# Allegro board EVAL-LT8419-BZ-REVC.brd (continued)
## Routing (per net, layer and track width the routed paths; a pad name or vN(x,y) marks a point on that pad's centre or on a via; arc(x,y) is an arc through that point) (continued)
SAC2: length 72
  TOP w0.203: C742.1 115,46.44 115.55,45.89 U7.22 ; R459.1 115.56,49.88
  L7_SIG w0.508: v1(58.05,61.13) 58.05,59.24 59.46,57.82 88.6,57.82 98.4,48.02 111.85,48.02 112.22,48.39 v3(115,48.39)
  BOTTOM w0.508: v1(58.05,61.13) 56.17,63.01 R717.2
SAC3: length 35.6
  TOP w0.203: C776.1 113.81,46.44 115.05,45.2 U7.23
  L7_SIG w0.508: v1(87.39,64.28) 87.42,64.31 88.35,64.31 88.79,63.88 88.79,60.83 92.12,57.5 107.21,57.5 111.43,53.28 v3(111.43,51.58)
SAC4: length 56.4
  TOP w0.203: v3(115.4,28.99) 115.36,29.03 C826.1 115.05,29.95 U7.58
  L6_SIG w0.508: v1(121.05,63.62) 121.08,63.65 121.9,63.65 123.27,62.28 123.27,48.09 118.03,42.85 118.03,37.65 117.22,36.83 111.25,36.83 109.58,35.17 109.58,33.31 108.71,32.44 108.71,30.07 109.79,28.99 v3(115.4,28.99)
  BOTTOM w0.203: v1(121.05,63.62) 120.78,63.9 R807.2
SAC5: length 62.7
  TOP w0.203: U7.59 115.55,31.42 116.55,30.42 v3(116.55,29.65)
  L7_SIG w0.508: v3(116.55,29.65) 118.23,29.65 120.86,32.27 128.45,32.27 140.54,44.36 145.18,44.36 146.27,45.44 146.27,52.12 155.05,60.9 v1(155.05,63.61)
  BOTTOM w0.203: R819.2 v1(155.05,63.61)
SAC6: length 91.7
  TOP w0.203: v3(124.19,29.07) 124.2,29.08 C896.1 124.2,29.67 121.28,32.59 U7.64
  L7_SIG w0.508: v1(185.56,63.09) 184.83,62.36 180.08,62.36 173.17,55.44 173.17,42.88 165.07,34.78 135.45,34.78 129.74,29.07 v3(124.19,29.07)
  BOTTOM w0.203: R830.2 v1(185.56,63.09)
SCL: length 149.3
  TOP w0.203: v3(107.5,38.1) 107.62,38.23 107.62,38.33 107.88,38.59 U7.40
  L6_SIG w0.203: v1(5.56,14.28) 5.56,17.01 3.95,18.61 3.95,44.21 E29.1
  L7_SIG w0.203: v1(5.56,14.28) 6.35,13.49 9.12,13.49 11.23,15.6 19.44,15.6 20.82,16.99 30.17,16.99 36.76,23.59 65.74,23.59 76.26,34.11 102.62,34.11 105.95,37.44 107.07,37.44 107.5,37.87 v3(107.5,38.1)
  BOTTOM w0.203: R415.2 v1(5.56,14.28)
SDA: length 158.2
  TOP w0.203: U7.39 107.72,39.09 107.39,38.76 107.39,38.66 107.04,38.3 107.04,38.15 v3(106.99,38.1)
  L6_SIG w0.203: v1(8.7,14.28) 8.14,14.84 6.9,14.84 6.57,14.51 6.57,14.5 5.79,13.72 5.33,13.72 5,14.05 5,16.99 3.55,18.44 3.55,51.42 E32.1
  L7_SIG w0.203: v1(8.7,14.28) 10.51,16.09 19.28,16.09 20.67,17.48 29,17.48 35.61,24.1 65.67,24.1 76.09,34.52 102.39,34.52 105.73,37.85 106.74,37.85 v3(106.99,38.1)
  BOTTOM w0.203: R12.2 v1(8.7,14.28)
SDC1: length 11
  TOP w0.203: R458.2 120.83,51.08 120.5,50.76 119.95,50.76 119.57,50.38 R708.2 119.23,49.88 119.03,49.68 119.03,47.79 119.8,47.01 C14.1 119.83,46.35 119,45.52 117.7,45.52 117.05,44.87 U7.19
SDC2: length 9.6
  TOP w0.203: R459.2 116.83,51.08 117.21,50.7 117.75,50.7 118.07,50.38 R719.2 118.42,49.88 118.62,49.68 118.62,47.79 117.84,47.01 C743.1 117.82,46.44 117.21,45.83 116.55,45.17 U7.20
SDC3: length 9.6
  TOP w0.203: U7.25 114.05,45.04 113.29,45.8 112.21,45.8 111.74,46.26 111.16,46.26 110.99,46.44 C783.1 110.96,47.01 110.19,47.79 R729.2 R460.2
SDC4: length 8.3
  TOP w0.203: R461.2 R809.2 111.74,29.47 111.94,29.67 C827.1 112.54,30.33 114.05,31.84 U7.56
SDC5: length 11.2
  TOP w0.203: R462.2 118.38,25.74 118.6,25.96 119.42,25.96 119.62,26.16 R820.2 119.97,26.8 120.17,27.01 120.17,28.9 119.4,29.67 C861.1 119.37,30.24 118.76,30.85 117.43,30.85 116.55,31.73 U7.61
SDC6: length 12.6
  TOP w0.203: R463.2 122.37,25.71 122.12,25.96 121.47,25.96 121.12,26.31 R831.2 120.78,26.8 120.58,27.01 120.58,28.9 121.35,29.67 ; 121.35,29.67 121.35,30.24 120.36,31.23 117.59,31.23 117.05,31.77 U7.62 ; 121.35,29.67 C895.1
SDO: length 179.7
  TOP w0.203: U7.38 107.68,39.59 v3(106.94,38.85)
  L6_SIG w0.203: J6.5 9.35,22.34 9.35,14.06 8.95,13.66 7.75,13.66 v1(7.13,14.28) 6.16,13.32 5.16,13.32 4.59,13.88 4.59,16.82 3.14,18.27 3.14,58.63 E30.1
  L7_SIG w0.203: v1(7.13,14.28) 9.37,16.52 19.06,16.52 20.55,18.01 27.67,18.01 34.16,24.5 65.51,24.5 75.92,34.92 102.14,34.92 105.61,38.39 106.62,38.39 106.94,38.71 v3(106.94,38.85)
  BOTTOM w0.203: R417.2 v1(7.13,14.28)
SN1: length 480.9
  TOP w0.203: v3(112.54,28.07) 113.38,28.07 R810.2 ; R833.2 122.22,28.07 v3(121.38,28.07) ; v3(119.37,28.07) 118.53,28.07 R822.2
  TOP w0.254: U7.57 114.55,31.06 113.76,30.27 C826.2 ; U7.60 116.05,31.52 117.13,30.45 117.97,30.45 118.15,30.27 C860.2 ; C742.2 116.6,46.42 116.05,45.87 U7.21 ; U7.18 117.55,44.8 117.81,45.06 119.76,45.06 121.02,46.32 C715.2 ; C776.2 112.21,47.01 112.98,46.24 113.43,46.24 114.55,45.12 U7.24 ; C896.2 122.6,30.34 121.29,31.64 117.76,31.64 117.55,31.85 U7.63
  L5_GND w0.508: v2(142.55,26.54) 141.93,25.91 130.95,25.91 129.18,27.68 129.18,43.42 126.77,45.83 v1(124.62,45.83)
  L7_SIG w0.254: v1(200.62,52.18) 201.98,52.18 218.26,68.47 v3(218.26,73.55)
  L7_SIG w0.305: v2(36.28,53.07) 36.28,53.48 36.98,54.18 46.28,54.18 48.33,52.13 48.33,48.24 54.37,42.2 106.47,42.2 107.41,41.26 114.27,41.26 119.83,46.82 v3(119.83,48.61) ; v3(117.82,48.61) 115.26,46.05 109.01,46.05 108.15,45.19 84.23,45.19 75.27,54.15 65.9,54.15 65.23,53.48 v2(65.23,53.07) ; v3(112.54,28.07) 112.54,27.35 110.75,25.56 110.75,24.63 111.3,24.08 112.23,24.08 114.86,26.71 114.86,29.32 120.45,34.92 120.45,38.53 121.28,39.35 122.29,39.35 123.53,38.11 130.11,38.11 132.25,40.24 132.25,49.17 130.47,50.94 130.47,53.77 130.93,54.23 133.76,54.23 134.1,53.89 v2(134.1,53.07) ; v3(110.99,48.66) 110.99,49.4 106.21,54.18 97.14,54.18 96.44,53.48 v2(96.44,53.07) ; v2(194.26,53.07) 194.26,53.48 193.54,54.2 185.16,54.2 181.65,50.7 181.65,46 167.5,31.85 144.13,31.85 135.4,23.12 121.77,23.12 120.41,24.47 120.41,27.11 v3(121.38,28.07) ; v3(119.37,28.07) 119.78,28.07 121.81,30.11 129.16,30.11 138.13,39.08 146.78,39.08 150.81,43.1 150.81,48.86 156.14,54.2 164.59,54.2 165.31,53.48 v2(165.31,53.07)
  vias: v1(102.4,40.1) v2(23.37,13.21) v2(23.37,3.05) v2(25.91,25.91) v2(25.91,15.75) v2(30.99,25.91) v2(30.99,15.75) v2(33.53,13.21) v2(33.53,3.05) v2(36.07,25.91) v2(36.07,15.75) v2(36.07,13.21) v2(36.07,10.67) v2(36.07,8.13) v2(36.07,5.59) v2(36.07,3.05) v2(38.61,13.21) v2(38.61,10.67) v2(38.61,8.13) v2(38.61,5.59) v2(38.61,3.05) v2(40.37,25.92) v2(41.15,15.75) v2(41.15,13.21) v2(41.15,10.67) v2(41.15,8.13) v2(41.15,5.59) v2(41.15,3.05) v2(41.31,29.34) v2(41.31,28.04) v2(41.27,26.65) v2(41.36,52.18) v2(41.36,50.91) v2(41.36,49.64) v2(41.36,48.37) v2(41.36,47.1) v2(41.36,45.83) v2(41.38,44.62) v2(41.38,43.35) v2(41.38,42.08) v2(42.52,26.63) v2(42.63,52.18) v2(42.63,50.91) v2(42.63,49.64) v2(42.63,48.37) v2(42.63,47.1) v2(42.63,45.83) v2(42.56,29.32) v2(42.56,28.03) v2(42.65,44.62) v2(42.65,43.35) v2(42.65,42.08) v2(42.66,40.93) v2(42.64,39.65) v2(43.69,13.21) v2(43.69,10.67) v2(43.69,8.13) v2(43.69,5.59) v2(43.69,3.05) v2(46.23,25.91) v2(46.23,15.75) v2(46.23,13.21) v2(46.23,10.67) v2(46.23,8.13) v2(46.23,5.59) v2(46.23,3.05) v2(48.77,13.21) v2(48.77,10.67) v2(48.77,8.13) v2(48.77,5.59) v2(48.77,3.05) v2(50.9,25.87) v2(51.31,15.75) v2(51.31,13.21) v2(51.31,10.67) v2(51.31,8.13) v2(51.31,5.59) v2(51.31,3.05) v2(51.91,29.25) v2(51.91,27.95) v2(51.87,26.56) v2(53.12,26.54) v2(53.16,29.23) v2(53.16,27.94) v2(53.85,13.21) v2(53.85,10.67) v2(53.85,8.13) v2(53.85,5.59) v2(53.85,3.05) v2(56.39,25.91) v2(56.39,15.75) v2(56.39,13.21) v2(56.39,10.67) v2(56.39,5.59) v2(56.39,3.05) v2(58.88,52.18) v2(58.88,50.91) v2(58.88,49.64) v2(58.88,48.37) v2(58.88,47.1) v2(58.88,45.83) v2(60.15,52.18) v2(60.15,50.91) v2(60.15,49.64) v2(60.15,48.37) v2(60.15,47.1) v2(60.15,45.83) v2(61.47,25.91) v2(61.47,15.75) v2(62.61,29.41) v2(62.61,28.12) v2(62.58,26.72) v2(63.83,26.7) v2(63.86,29.4) v2(63.86,28.1) v2(66.55,15.75) v2(69.09,13.21) v2(69.09,10.67) v2(69.09,5.59) v2(69.09,3.05) v2(69.81,25.94) v2(70.31,52.18) v2(70.31,50.91) v2(70.31,49.64) v2(70.31,48.37) v2(70.31,47.1) v2(70.31,45.83) v2(71.58,52.18) v2(71.58,50.91) v2(71.58,49.64) v2(71.58,48.37) v2(71.58,47.1) v2(71.58,45.83) v2(71.63,25.91) v2(71.63,15.75) v2(71.63,13.21) v2(71.63,10.67) v2(71.63,8.13) v2(71.63,5.59) v2(71.63,3.05) v2(72.91,29.46) v2(72.91,28.16) v2(72.88,26.77) v2(74.13,26.75) v2(74.16,29.45) v2(74.16,28.15) v2(74.17,13.21) v2(74.17,10.67) v2(74.17,8.13) v2(74.17,5.59) v2(74.17,3.05) v2(76.71,25.91) v2(76.71,15.75) v2(76.71,13.21) v2(76.71,10.67) v2(76.71,8.13) v2(76.71,5.59) v2(76.71,3.05) v2(79.25,13.21) v2(79.25,10.67) v2(79.25,8.13) v2(79.25,5.59) v2(79.25,3.05) v2(81.79,25.91) v2(81.79,15.75) v2(81.79,13.21) v2(81.79,10.67) v2(81.79,8.13) v2(81.79,5.59) v2(81.79,3.05) v2(83.42,29.43) v2(83.42,28.13) v2(83.39,26.73) v2(84.33,13.21) v2(84.33,10.67) v2(84.33,8.13) v2(84.33,5.59) v2(84.33,3.05) v2(84.64,26.72) v2(84.67,29.41) v2(84.67,28.12) v2(86.87,25.91) v2(86.87,15.75) v2(86.87,13.21) v2(86.87,10.67) v2(86.87,8.13) v2(86.87,5.59) v2(86.87,3.05) v2(89.41,13.21) v2(89.41,10.67) v2(89.41,8.13) v2(89.41,5.59) v2(89.41,3.05) v2(90.09,52.18) v2(90.09,50.91) v2(90.09,49.64) v2(90.09,48.37) v2(90.09,47.1) v2(90.09,45.83) v2(91.36,52.18) v2(91.36,50.91) v2(91.36,49.64) v2(91.36,48.37) v2(91.36,47.1) v2(91.36,45.83) v2(91.95,25.91) v2(91.95,15.75) v2(91.95,13.21) v2(91.95,3.05) v2(93.42,29.56) v2(93.43,28.26) v2(93.39,26.87) v2(94.67,29.54) v2(94.67,28.25) v2(94.64,26.85) v2(97.03,25.91) v2(97.03,15.75) v2(102.11,20.83) v2(102.11,15.75) v2(102.11,13.21) v2(102.11,3.05) v2(107.19,20.83) v2(107.19,15.75) v2(107.19,10.67) v2(107.19,5.59) v2(112.27,15.75) v2(112.27,10.67) v2(112.27,5.59) v2(117.35,20.83) v2(122.43,20.83) v2(127.51,20.83) v2(132.59,20.83) v2(137.67,20.83) v2(139.18,52.18) v2(139.18,50.91) v2(139.18,49.64) v2(139.18,48.37) v2(139.18,47.1) v2(139.18,45.83) v2(140.45,52.18) v2(140.45,50.91) v2(140.45,49.64) v2(140.45,48.37) v2(140.45,47.1) v2(140.45,45.83) v2(142.59,29.23) v2(142.59,27.94) v2(143.84,29.22) v2(143.84,27.92) v2(143.8,26.52) v2(144.68,20.81) v2(147.83,20.83) v2(152.53,29.22) v2(152.53,28.04) v2(152.49,26.52) v2(153.77,29.2) v2(153.78,28.03) v2(153.74,26.51) v2(154.7,20.8) v2(157.99,20.83) v2(158.96,52.18) v2(158.96,50.91) v2(158.96,49.64) v2(158.96,48.37) v2(158.96,47.1) v2(158.96,45.83) v2(160.23,52.18) v2(160.23,50.91) v2(160.23,49.64) v2(160.23,48.37) v2(160.23,47.1) v2(160.23,45.83) v2(162.48,29.02) v2(162.48,28.1) v2(162.45,26.33) v2(163.73,29.01) v2(163.73,28.08) v2(163.7,26.31) v2(164.73,20.77) v2(168.15,20.83) v2(170.39,52.18) v2(170.39,50.91) v2(170.39,49.64) v2(170.39,48.37) v2(170.39,47.1) v2(170.39,45.83) v2(171.66,52.18) v2(171.66,50.91) v2(171.66,49.64) v2(171.66,48.37) v2(171.66,47.1) v2(171.66,45.83) v2(172.03,29.15) v2(172,26.46) v2(172.06,28.05) v2(173.28,29.14) v2(173.31,28.03) v2(173.25,26.44) v2(174.31,20.81) v2(178.31,20.83) v2(181.92,26.6) v2(181.95,29.3) v2(181.95,28) v2(183.2,29.28) v2(183.2,27.98) v2(183.17,26.59) v2(184.15,20.89) v2(187.91,52.18) v2(187.91,50.91) v2(187.91,49.64) v2(187.93,48.39) v2(187.93,47.12) v2(187.93,45.85) v2(187.95,44.64) v2(187.98,43.25) v2(187.98,41.95) v2(187.95,40.55) v2(188.47,20.83) v2(189.18,52.18) v2(189.18,50.91) v2(189.18,49.64) v2(189.18,48.37) v2(189.18,47.1) v2(189.18,45.83) v2(189.2,44.63) v2(189.23,43.23) v2(189.23,41.93) v2(189.2,40.54) v2(191.62,26.7) v2(191.65,29.4) v2(191.65,28.1) v2(192.9,29.38) v2(192.9,28.08) v2(192.87,26.68) v2(193.78,20.85) v2(198.63,20.83) v3(130.89,27.92) v3(139.5,54.12)
VHIGH: length 483.2
  TOP w0.508: 130.98,40.79 R429.1 131.14,40.74 130.5,40.74 ; v1(128.2,40.56) R1.2 129.09,40.56
  L2_PWR w0.508: v3(36.65,74.43) v3(37.15,74.43) ; v3(36.65,79) v3(37.15,79) ; v3(36.65,71.38) v3(37.15,71.38) ; v3(36.65,72.92) v3(37.15,72.92) ; v3(37.15,77.48) v3(36.65,77.48) ; v3(36.65,75.95) v3(37.15,75.95)
  L5_GND w0.508: v3(197.23,76.48) v3(197.61,76.48) v3(197.99,76.48) v3(198.37,76.48) v3(198.75,76.48) v3(199.14,76.48) v3(199.52,76.48) v3(199.9,76.48) v3(200.28,76.48) ; v3(130.62,72.92) v3(130.11,72.92) ; v3(36.65,77.48) v3(37.15,77.48) ; 135.76,74.53 v3(135.76,74.72) v3(135.38,74.72) v3(135,74.72) v3(134.62,74.72) v3(134.24,74.72) v3(133.86,74.72) v3(133.48,74.72) v3(133.1,74.72) v3(132.71,74.72) 132.71,74.53 ; 135.76,74.53 132.71,74.53 ; 135.76,74.53 v3(135.76,74.34) v3(135.38,74.34) v3(135,74.34) v3(134.62,74.34) v3(134.24,74.34) v3(133.86,74.34) v3(133.48,74.34) v3(133.1,74.34) v3(132.71,74.34) 132.71,74.53 ; v3(65.6,77.48) v3(66.1,77.48) ; 171.33,74.53 v3(171.33,74.72) v3(170.95,74.72) v3(170.57,74.72) v3(170.18,74.72) v3(169.8,74.72) v3(169.42,74.72) v3(169.04,74.72) v3(168.66,74.72) v3(168.28,74.72) 168.28,74.53 ; 171.33,74.53 168.28,74.53 ; 171.33,74.53 v3(171.33,74.34) v3(170.95,74.34) v3(170.57,74.34) v3(170.18,74.34) v3(169.8,74.34) v3(169.42,74.34) v3(169.04,74.34) v3(168.66,74.34) v3(168.28,74.34) 168.28,74.53 ; v3(130.11,77.48) v3(130.62,77.48) ; 106.81,74.53 v3(106.81,74.72) v3(106.43,74.72) v3(106.05,74.72) v3(105.67,74.72) v3(105.29,74.72) v3(104.91,74.72) v3(104.53,74.72) v3(104.14,74.72) v3(103.76,74.72) 103.76,74.53 ; 106.81,74.53 v3(106.81,74.34) v3(106.43,74.34) v3(106.05,74.34) v3(105.67,74.34) v3(105.29,74.34) v3(104.91,74.34) v3(104.53,74.34) v3(104.14,74.34) v3(103.76,74.34) 103.76,74.53 ; 106.81,74.53 103.76,74.53 ; v3(166.19,71.38) v3(165.68,71.38) ; v3(68.2,78.18) v3(68.58,78.18) v3(68.96,78.18) v3(69.34,78.18) v3(69.72,78.18) v3(70.1,78.18) v3(70.48,78.18) v3(70.87,78.18) v3(71.25,78.18) ; v3(37.15,75.95) v3(36.65,75.95) ; 68.2,74.53 v3(68.2,74.72) v3(68.58,74.72) v3(68.96,74.72) v3(69.34,74.72) v3(69.72,74.72) v3(70.1,74.72) v3(70.48,74.72) v3(70.87,74.72) v3(71.25,74.72) 71.25,74.53 ; 68.2,74.53 71.25,74.53 ; 68.2,74.53 v3(68.2,74.34) v3(68.58,74.34) v3(68.96,74.34) v3(69.34,74.34) v3(69.72,74.34) v3(70.1,74.34) v3(70.48,74.34) v3(70.87,74.34) v3(71.25,74.34) 71.25,74.53 ; v3(42.3,76.48) v3(41.91,76.48) v3(41.53,76.48) v3(41.15,76.48) v3(40.77,76.48) v3(40.39,76.48) v3(40.01,76.48) v3(39.63,76.48) v3(39.25,76.48) ; v3(200.28,78.18) v3(199.9,78.18) v3(199.52,78.18) v3(199.14,78.18) v3(198.75,78.18) v3(198.37,78.18) v3(197.99,78.18) v3(197.61,78.18) v3(197.23,78.18) ; v3(130.62,74.43) v3(130.11,74.43) ; v3(106.81,78.18) v3(106.43,78.18) v3(106.05,78.18) v3(105.67,78.18) v3(105.29,78.18) v3(104.91,78.18) v3(104.53,78.18) v3(104.14,78.18) v3(103.76,78.18) ; v3(168.28,78.18) v3(168.66,78.18) v3(169.04,78.18) v3(169.42,78.18) v3(169.8,78.18) v3(170.18,78.18) v3(170.57,78.18) v3(170.95,78.18) v3(171.33,78.18) ; v3(132.71,76.48) v3(133.1,76.48) v3(133.48,76.48) v3(133.86,76.48) v3(134.24,76.48) v3(134.62,76.48) v3(135,76.48) v3(135.38,76.48) v3(135.76,76.48) ; v3(66.1,75.95) v3(65.6,75.95) ; 197.23,74.53 200.28,74.53 ; 197.23,74.53 v3(197.23,74.34) v3(197.61,74.34) v3(197.99,74.34) v3(198.37,74.34) v3(198.75,74.34) v3(199.14,74.34) v3(199.52,74.34) v3(199.9,74.34) v3(200.28,74.34) 200.28,74.53 ; 197.23,74.53 v3(197.23,74.72) v3(197.61,74.72) v3(197.99,74.72) v3(198.37,74.72) v3(198.75,74.72) v3(199.14,74.72) v3(199.52,74.72) v3(199.9,74.72) v3(200.28,74.72) 200.28,74.53 ; v3(195.14,72.92) v3(194.63,72.92) ; v3(66.1,72.92) v3(65.6,72.92) ; 39.25,74.53 v3(39.25,74.72) v3(39.63,74.72) v3(40.01,74.72) v3(40.39,74.72) v3(40.77,74.72) v3(41.15,74.72) v3(41.53,74.72) v3(41.91,74.72) v3(42.3,74.72) 42.3,74.53 ; 39.25,74.53 42.3,74.53 ; 39.25,74.53 v3(39.25,74.34) v3(39.63,74.34) v3(40.01,74.34) v3(40.39,74.34) v3(40.77,74.34) v3(41.15,74.34) v3(41.53,74.34) v3(41.91,74.34) v3(42.3,74.34) 42.3,74.53 ; v3(165.68,79) v3(166.19,79) ; v3(71.25,76.48) v3(70.87,76.48) v3(70.48,76.48) v3(70.1,76.48) v3(69.72,76.48) v3(69.34,76.48) v3(68.96,76.48) v3(68.58,76.48) v3(68.2,76.48) ; v3(106.81,76.48) v3(106.43,76.48) v3(106.05,76.48) v3(105.67,76.48) v3(105.29,76.48) v3(104.91,76.48) v3(104.53,76.48) v3(104.14,76.48) v3(103.76,76.48) ; v3(135.76,78.18) v3(135.38,78.18) v3(135,78.18) v3(134.62,78.18) v3(134.24,78.18) v3(133.86,78.18) v3(133.48,78.18) v3(133.1,78.18) v3(132.71,78.18) ; v3(42.3,78.18) v3(41.91,78.18) v3(41.53,78.18) v3(41.15,78.18) v3(40.77,78.18) v3(40.39,78.18) v3(40.01,78.18) v3(39.63,78.18) v3(39.25,78.18) ; v3(166.19,75.95) v3(165.68,75.95) ; v3(37.15,74.43) v3(36.65,74.43) ; v3(194.63,77.48) v3(195.14,77.48) ; v3(101.67,71.38) v3(101.16,71.38) ; v3(195.14,74.43) v3(194.63,74.43) ; v3(195.14,71.38) v3(194.63,71.38) ; v3(130.62,71.38) v3(130.11,71.38) ; v3(101.67,74.43) v3(101.16,74.43) ; v3(101.16,77.48) v3(101.67,77.48) ; v1(129.24,46.31) 129.24,46.69 128.74,47.2 117.86,47.2 115.46,49.6 115.46,54.7 114.88,55.28 114.88,108.4 v2(116.71,110.24) ; v3(194.63,79) v3(195.14,79) ; v3(36.65,79) v3(37.15,79) ; v3(37.15,71.38) v3(36.65,71.38) ; v3(165.68,77.48) v3(166.19,77.48) ; v3(171.33,76.48) v3(170.95,76.48) v3(170.57,76.48) v3(170.18,76.48) v3(169.8,76.48) v3(169.42,76.48) v3(169.04,76.48) v3(168.66,76.48) v3(168.28,76.48) ; v3(66.1,71.38) v3(65.6,71.38) ; v3(101.16,79) v3(101.67,79) ; v3(37.15,72.92) v3(36.65,72.92) ; v3(195.14,75.95) v3(194.63,75.95) ; v3(130.11,79) v3(130.62,79) ; v3(166.19,74.43) v3(165.68,74.43) ; v3(66.1,74.43) v3(65.6,74.43) ; v3(101.67,75.95) v3(101.16,75.95) ; v3(166.19,72.92) v3(165.68,72.92) ; v3(65.6,79) v3(66.1,79) ; v3(101.67,72.92) v3(101.16,72.92) ; v3(130.62,75.95) v3(130.11,75.95)
  L6_SIG w0.508: v3(37.15,77.48) v3(36.65,77.48) ; v3(71.25,78.18) v3(70.87,78.18) v3(70.48,78.18) v3(70.1,78.18) v3(69.72,78.18) v3(69.34,78.18) v3(68.96,78.18) v3(68.58,78.18) v3(68.2,78.18) ; v3(66.1,74.43) v3(65.6,74.43) ; v3(197.23,78.18) v3(197.61,78.18) v3(197.99,78.18) v3(198.37,78.18) v3(198.75,78.18) v3(199.14,78.18) v3(199.52,78.18) v3(199.9,78.18) v3(200.28,78.18) ; v3(39.25,78.18) v3(39.63,78.18) v3(40.01,78.18) v3(40.39,78.18) v3(40.77,78.18) v3(41.15,78.18) v3(41.53,78.18) v3(41.91,78.18) v3(42.3,78.18) ; 103.76,74.53 v3(103.76,74.72) v3(104.14,74.72) v3(104.53,74.72) v3(104.91,74.72) v3(105.29,74.72) v3(105.67,74.72) v3(106.05,74.72) v3(106.43,74.72) v3(106.81,74.72) 106.81,74.53 ; 103.76,74.53 v3(103.76,74.34) v3(104.14,74.34) v3(104.53,74.34) v3(104.91,74.34) v3(105.29,74.34) v3(105.67,74.34) v3(106.05,74.34) v3(106.43,74.34) v3(106.81,74.34) 106.81,74.53 ; 103.76,74.53 106.81,74.53 ; 200.28,74.53 v3(200.28,74.34) v3(199.9,74.34) v3(199.52,74.34) v3(199.14,74.34) v3(198.75,74.34) v3(198.37,74.34) v3(197.99,74.34) v3(197.61,74.34) v3(197.23,74.34) 197.23,74.53 ; 200.28,74.53 v3(200.28,74.72) v3(199.9,74.72) v3(199.52,74.72) v3(199.14,74.72) v3(198.75,74.72) v3(198.37,74.72) v3(197.99,74.72) v3(197.61,74.72) v3(197.23,74.72) 197.23,74.53 ; 200.28,74.53 197.23,74.53 ; 132.71,74.53 135.76,74.53 ; 132.71,74.53 v3(132.71,74.72) v3(133.1,74.72) v3(133.48,74.72) v3(133.86,74.72) v3(134.24,74.72) v3(134.62,74.72) v3(135,74.72) v3(135.38,74.72) v3(135.76,74.72) 135.76,74.53 ; 132.71,74.53 v3(132.71,74.34) v3(133.1,74.34) v3(133.48,74.34) v3(133.86,74.34) v3(134.24,74.34) v3(134.62,74.34) v3(135,74.34) v3(135.38,74.34) v3(135.76,74.34) 135.76,74.53 ; v3(166.19,77.48) v3(165.68,77.48) ; v3(195.14,74.43) v3(194.63,74.43) ; v3(165.68,79) v3(166.19,79) ; v3(68.2,76.48) v3(68.58,76.48) v3(68.96,76.48) v3(69.34,76.48) v3(69.72,76.48) v3(70.1,76.48) v3(70.48,76.48) v3(70.87,76.48) v3(71.25,76.48) ; v3(194.63,75.95) v3(195.14,75.95) ; v3(106.81,78.18) v3(106.43,78.18) v3(106.05,78.18) v3(105.67,78.18) v3(105.29,78.18) v3(104.91,78.18) v3(104.53,78.18) v3(104.14,78.18) v3(103.76,78.18) ; v3(130.11,79) v3(130.62,79) ; v3(197.23,76.48) v3(197.61,76.48) v3(197.99,76.48) v3(198.37,76.48) v3(198.75,76.48) v3(199.14,76.48) v3(199.52,76.48) v3(199.9,76.48) v3(200.28,76.48) ; v3(135.76,76.48) v3(135.38,76.48) v3(135,76.48) v3(134.62,76.48) v3(134.24,76.48) v3(133.86,76.48) v3(133.48,76.48) v3(133.1,76.48) v3(132.71,76.48) ; 42.3,74.53 v3(42.3,74.72) v3(41.91,74.72) v3(41.53,74.72) v3(41.15,74.72) v3(40.77,74.72) v3(40.39,74.72) v3(40.01,74.72) v3(39.63,74.72) v3(39.25,74.72) 39.25,74.53 ; 42.3,74.53 39.25,74.53 ; 42.3,74.53 v3(42.3,74.34) v3(41.91,74.34) v3(41.53,74.34) v3(41.15,74.34) v3(40.77,74.34) v3(40.39,74.34) v3(40.01,74.34) v3(39.63,74.34) v3(39.25,74.34) 39.25,74.53 ; v3(101.16,75.95) v3(101.67,75.95) ; 71.25,74.53 v3(71.25,74.34) v3(70.87,74.34) v3(70.48,74.34) v3(70.1,74.34) v3(69.72,74.34) v3(69.34,74.34) v3(68.96,74.34) v3(68.58,74.34) v3(68.2,74.34) 68.2,74.53 ; 71.25,74.53 v3(71.25,74.72) v3(70.87,74.72) v3(70.48,74.72) v3(70.1,74.72) v3(69.72,74.72) v3(69.34,74.72) v3(68.96,74.72) v3(68.58,74.72) v3(68.2,74.72) 68.2,74.53 ; 71.25,74.53 68.2,74.53 ; 168.28,74.53 171.33,74.53 ; 168.28,74.53 v3(168.28,74.72) v3(168.66,74.72) v3(169.04,74.72) v3(169.42,74.72) v3(169.8,74.72) v3(170.18,74.72) v3(170.57,74.72) v3(170.95,74.72) v3(171.33,74.72) 171.33,74.53 ; 168.28,74.53 v3(168.28,74.34) v3(168.66,74.34) v3(169.04,74.34) v3(169.42,74.34) v3(169.8,74.34) v3(170.18,74.34) v3(170.57,74.34) v3(170.95,74.34) v3(171.33,74.34) 171.33,74.53 ; v3(130.62,74.43) v3(130.11,74.43) ; v3(37.15,74.43) v3(36.65,74.43) ; v3(36.65,75.95) v3(37.15,75.95) ; v3(36.65,72.92) v3(37.15,72.92) ; v3(171.33,78.18) v3(170.95,78.18) v3(170.57,78.18) v3(170.18,78.18) v3(169.8,78.18) v3(169.42,78.18) v3(169.04,78.18) v3(168.66,78.18) v3(168.28,78.18) ; v3(101.16,79) v3(101.67,79) ; v3(165.68,75.95) v3(166.19,75.95) ; v3(42.3,76.48) v3(41.91,76.48) v3(41.53,76.48) v3(41.15,76.48) v3(40.77,76.48) v3(40.39,76.48) v3(40.01,76.48) v3(39.63,76.48) v3(39.25,76.48) ; v3(195.14,77.48) v3(194.63,77.48) ; v3(194.63,79) v3(195.14,79) ; v3(171.33,76.48) v3(170.95,76.48) v3(170.57,76.48) v3(170.18,76.48) v3(169.8,76.48) v3(169.42,76.48) v3(169.04,76.48) v3(168.66,76.48) v3(168.28,76.48) ; v3(101.67,77.48) v3(101.16,77.48) ; v3(65.6,79) v3(66.1,79) ; v3(132.71,78.18) v3(133.1,78.18) v3(133.48,78.18) v3(133.86,78.18) v3(134.24,78.18) v3(134.62,78.18) v3(135,78.18) v3(135.38,78.18) v3(135.76,78.18) ; v3(36.65,79) v3(37.15,79) ; v3(65.6,75.95) v3(66.1,75.95) ; v3(106.81,76.48) v3(106.43,76.48) v3(106.05,76.48) v3(105.67,76.48) v3(105.29,76.48) v3(104.91,76.48) v3(104.53,76.48) v3(104.14,76.48) v3(103.76,76.48) ; v3(101.67,74.43) v3(101.16,74.43) ; v3(130.62,77.48) v3(130.11,77.48) ; v3(166.19,74.43) v3(165.68,74.43) ; v3(130.11,75.95) v3(130.62,75.95) ; v3(66.1,77.48) v3(65.6,77.48)
  L7_SIG w0.508: v3(39.25,78.18) v3(39.63,78.18) v3(40.01,78.18) v3(40.39,78.18) v3(40.77,78.18) v3(41.15,78.18) v3(41.53,78.18) v3(41.91,78.18) v3(42.3,78.18) ; 135.76,74.53 v3(135.76,74.72) v3(135.38,74.72) v3(135,74.72) v3(134.62,74.72) v3(134.24,74.72) v3(133.86,74.72) v3(133.48,74.72) v3(133.1,74.72) v3(132.71,74.72) 132.71,74.53 ; 135.76,74.53 132.71,74.53 ; 135.76,74.53 v3(135.76,74.34) v3(135.38,74.34) v3(135,74.34) v3(134.62,74.34) v3(134.24,74.34) v3(133.86,74.34) v3(133.48,74.34) v3(133.1,74.34) v3(132.71,74.34) 132.71,74.53 ; v3(130.62,77.48) v3(130.11,77.48) ; 197.23,74.53 200.28,74.53 ; 197.23,74.53 v3(197.23,74.72) v3(197.61,74.72) v3(197.99,74.72) v3(198.37,74.72) v3(198.75,74.72) v3(199.14,74.72) v3(199.52,74.72) v3(199.9,74.72) v3(200.28,74.72) 200.28,74.53 ; 197.23,74.53 v3(197.23,74.34) v3(197.61,74.34) v3(197.99,74.34) v3(198.37,74.34) v3(198.75,74.34) v3(199.14,74.34) v3(199.52,74.34) v3(199.9,74.34) v3(200.28,74.34) 200.28,74.53 ; v3(66.1,71.38) v3(65.6,71.38) ; v3(200.28,78.18) v3(199.9,78.18) v3(199.52,78.18) v3(199.14,78.18) v3(198.75,78.18) v3(198.37,78.18) v3(197.99,78.18) v3(197.61,78.18) v3(197.23,78.18) ; v3(101.16,75.95) v3(101.67,75.95) ; 103.76,74.53 v3(103.76,74.72) v3(104.14,74.72) v3(104.53,74.72) v3(104.91,74.72) v3(105.29,74.72) v3(105.67,74.72) v3(106.05,74.72) v3(106.43,74.72) v3(106.81,74.72) 106.81,74.53 ; 103.76,74.53 106.81,74.53 ; 103.76,74.53 v3(103.76,74.34) v3(104.14,74.34) v3(104.53,74.34) v3(104.91,74.34) v3(105.29,74.34) v3(105.67,74.34) v3(106.05,74.34) v3(106.43,74.34) v3(106.81,74.34) 106.81,74.53 ; v3(42.3,76.48) v3(41.91,76.48) v3(41.53,76.48) v3(41.15,76.48) v3(40.77,76.48) v3(40.39,76.48) v3(40.01,76.48) v3(39.63,76.48) v3(39.25,76.48) ; v3(130.62,74.43) v3(130.11,74.43) ; v3(68.2,76.48) v3(68.58,76.48) v3(68.96,76.48) v3(69.34,76.48) v3(69.72,76.48) v3(70.1,76.48) v3(70.48,76.48) v3(70.87,76.48) v3(71.25,76.48) ; 168.28,74.53 v3(168.28,74.34) v3(168.66,74.34) v3(169.04,74.34) v3(169.42,74.34) v3(169.8,74.34) v3(170.18,74.34) v3(170.57,74.34) v3(170.95,74.34) v3(171.33,74.34) 171.33,74.53 ; 168.28,74.53 v3(168.28,74.72) v3(168.66,74.72) v3(169.04,74.72) v3(169.42,74.72) v3(169.8,74.72) v3(170.18,74.72) v3(170.57,74.72) v3(170.95,74.72) v3(171.33,74.72) 171.33,74.53 ; 168.28,74.53 171.33,74.53 ; v3(66.1,74.43) v3(65.6,74.43) ; v3(65.6,72.92) v3(66.1,72.92) ; v3(194.63,72.92) v3(195.14,72.92) ; v3(166.19,77.48) v3(165.68,77.48) ; v3(65.6,79) v3(66.1,79) ; v3(36.65,79) v3(37.15,79) ; v3(194.63,79) v3(195.14,79) ; v3(37.15,74.43) v3(36.65,74.43) ; v3(135.76,76.48) v3(135.38,76.48) v3(135,76.48) v3(134.62,76.48) v3(134.24,76.48) v3(133.86,76.48) v3(133.48,76.48) v3(133.1,76.48) v3(132.71,76.48) ; v3(195.14,71.38) v3(194.63,71.38) ; v3(168.28,76.48) v3(168.66,76.48) v3(169.04,76.48) v3(169.42,76.48) v3(169.8,76.48) v3(170.18,76.48) v3(170.57,76.48) v3(170.95,76.48) v3(171.33,76.48) ; v3(103.76,76.48) v3(104.14,76.48) v3(104.53,76.48) v3(104.91,76.48) v3(105.29,76.48) v3(105.67,76.48) v3(106.05,76.48) v3(106.43,76.48) v3(106.81,76.48) ; v3(130.11,72.92) v3(130.62,72.92) ; v3(130.11,79) v3(130.62,79) ; v3(37.15,77.48) v3(36.65,77.48) ; v3(130.62,71.38) v3(130.11,71.38) ; v3(66.1,77.48) v3(65.6,77.48) ; v3(168.28,78.18) v3(168.66,78.18) v3(169.04,78.18) v3(169.42,78.18) v3(169.8,78.18) v3(170.18,78.18) v3(170.57,78.18) v3(170.95,78.18) v3(171.33,78.18) ; 42.3,74.53 v3(42.3,74.72) v3(41.91,74.72) v3(41.53,74.72) v3(41.15,74.72) v3(40.77,74.72) v3(40.39,74.72) v3(40.01,74.72) v3(39.63,74.72) v3(39.25,74.72) 39.25,74.53 ; 42.3,74.53 39.25,74.53 ; 42.3,74.53 v3(42.3,74.34) v3(41.91,74.34) v3(41.53,74.34) v3(41.15,74.34) v3(40.77,74.34) v3(40.39,74.34) v3(40.01,74.34) v3(39.63,74.34) v3(39.25,74.34) 39.25,74.53 ; v3(101.67,71.38) v3(101.16,71.38) ; v3(65.6,75.95) v3(66.1,75.95) ; v3(130.11,75.95) v3(130.62,75.95) ; v3(101.67,74.43) v3(101.16,74.43) ; v1(103.65,26.83) 103.65,28.63 109.49,34.48 116.92,34.48 118.23,35.79 118.23,39.45 121.79,43.01 125.75,43.01 v1(128.2,40.56) 129.24,41.6 v1(129.24,46.31) ; v3(101.67,77.48) v3(101.16,77.48) ; v3(197.23,76.48) v3(197.61,76.48) v3(197.99,76.48) v3(198.37,76.48) v3(198.75,76.48) v3(199.14,76.48) v3(199.52,76.48) v3(199.9,76.48) v3(200.28,76.48) ; 68.2,74.53 v3(68.2,74.34) v3(68.58,74.34) v3(68.96,74.34) v3(69.34,74.34) v3(69.72,74.34) v3(70.1,74.34) v3(70.48,74.34) v3(70.87,74.34) v3(71.25,74.34) 71.25,74.53 ; 68.2,74.53 v3(68.2,74.72) v3(68.58,74.72) v3(68.96,74.72) v3(69.34,74.72) v3(69.72,74.72) v3(70.1,74.72) v3(70.48,74.72) v3(70.87,74.72) v3(71.25,74.72) 71.25,74.53 ; 68.2,74.53 71.25,74.53 ; v3(36.65,75.95) v3(37.15,75.95) ; v1(203.26,74.67) 212.93,74.67 v3(218.06,79.81) ; v3(101.16,72.92) v3(101.67,72.92) ; v3(36.65,72.92) v3(37.15,72.92) ; v3(166.19,74.43) v3(165.68,74.43) ; v3(101.16,79) v3(101.67,79) ; v3(135.76,78.18) v3(135.38,78.18) v3(135,78.18) v3(134.62,78.18) v3(134.24,78.18) v3(133.86,78.18) v3(133.48,78.18) v3(133.1,78.18) v3(132.71,78.18) ; v3(165.68,75.95) v3(166.19,75.95) ; v3(37.15,71.38) v3(36.65,71.38) ; v3(165.68,72.92) v3(166.19,72.92) ; v3(106.81,78.18) v3(106.43,78.18) v3(106.05,78.18) v3(105.67,78.18) v3(105.29,78.18) v3(104.91,78.18) v3(104.53,78.18) v3(104.14,78.18) v3(103.76,78.18) ; v3(195.14,74.43) v3(194.63,74.43) ; v3(165.68,79) v3(166.19,79) ; v3(166.19,71.38) v3(165.68,71.38) ; v3(68.2,78.18) v3(68.58,78.18) v3(68.96,78.18) v3(69.34,78.18) v3(69.72,78.18) v3(70.1,78.18) v3(70.48,78.18) v3(70.87,78.18) v3(71.25,78.18) ; v3(195.14,77.48) v3(194.63,77.48) ; v3(194.63,75.95) v3(195.14,75.95)
  BOTTOM w0.508: C26.1 48.97,97.38 v2(48.78,97.57) ; C894.1 206.92,97.03 v2(206.22,97.73) ; v3(81,91.22) 80.79,91.01 80.79,91.9 C740.1
  vias: v1(39.42,73.58) v1(39.52,71.77) v1(39.85,72.67) v1(40.19,73.58) v1(40.28,71.77) v1(40.61,72.67) v1(40.95,73.58) v1(41.04,71.77) v1(41.38,72.67) v1(41.71,73.58) v1(41.81,71.77) v1(42.14,72.67) v1(42.47,73.58) v1(42.57,71.77) v1(43.32,79.08) v1(43.32,77.33) v1(43.32,75.57) v1(43.75,78.18) v1(43.75,76.42) v1(43.75,74.67) v1(44.08,79.08) v1(44.08,77.33) v1(44.08,75.57) v1(44.51,78.18) v1(44.51,76.42) v1(44.51,74.67) v1(44.84,79.08) v1(44.84,77.33) v1(44.84,75.57) v1(45.27,78.18) v1(45.27,76.42) v1(45.27,74.67) v1(68.37,73.58) v1(68.47,71.77) v1(68.8,72.67) v1(69.14,73.58) v1(69.23,71.77) v1(69.57,72.67) v1(69.9,73.58) v1(69.99,71.77) v1(70.33,72.67) v1(70.66,73.58) v1(70.76,71.77) v1(71.09,72.67) v1(71.42,73.58) v1(71.52,71.77) v1(72.27,79.08) v1(72.27,77.33) v1(72.27,75.57) v1(72.7,78.18) v1(72.7,76.42) v1(72.7,74.67) v1(73.03,79.08) v1(73.03,77.33) v1(73.03,75.57) v1(73.46,78.18) v1(73.46,76.42) v1(73.46,74.67) v1(73.8,79.08) v1(73.8,77.33) v1(73.8,75.57) v1(74.22,78.18) v1(74.22,76.42) v1(74.22,74.67) v1(103.94,73.58) v1(104.04,71.77) v1(104.37,72.67) v1(104.7,73.58) v1(104.8,71.77) v1(105.13,72.67) v1(105.46,73.58) v1(105.56,71.77) v1(105.89,72.67) v1(106.23,73.58) v1(106.32,71.77) v1(106.65,72.67) v1(106.99,73.58) v1(107.08,71.77) v1(107.84,79.08) v1(107.84,77.33) v1(107.84,75.57) v1(108.27,78.18) v1(108.27,76.42) v1(108.27,74.67) v1(108.6,79.08) v1(108.6,77.33) v1(108.6,75.57) v1(109.03,78.18) v1(109.03,76.42) v1(109.03,74.67) v1(109.36,79.08) v1(109.36,77.33) v1(109.36,75.57) v1(109.79,78.18) v1(109.79,76.42) v1(109.79,74.67) v1(132.89,73.58) v1(132.99,71.77) v1(133.32,72.67) v1(133.65,73.58) v1(133.75,71.77) v1(134.08,72.67) v1(134.41,73.58) v1(134.51,71.77) v1(134.84,72.67) v1(135.18,73.58) v1(135.27,71.77) v1(135.61,72.67) v1(135.94,73.58) v1(136.03,71.77) v1(136.79,79.08) v1(136.79,77.33) v1(136.79,75.57) v1(137.22,78.18) v1(137.22,76.42) v1(137.22,74.67) v1(137.55,79.08) v1(137.55,77.33) v1(137.55,75.57) v1(137.98,78.18) v1(137.98,76.42) v1(137.98,74.67) v1(138.31,79.08) v1(138.31,77.33) v1(138.31,75.57) v1(138.74,78.18) v1(138.74,76.42) v1(138.74,74.67) v1(168.46,73.58) v1(168.55,71.77) v1(168.88,72.67) v1(169.22,73.58) v1(169.31,71.77) v1(169.65,72.67) v1(169.98,73.58) v1(170.08,71.77) v1(170.41,72.67) v1(170.74,73.58) v1(170.84,71.77) v1(171.17,72.67) v1(171.5,73.58) v1(171.6,71.77) v1(172.35,79.08) v1(172.35,77.33) v1(172.35,75.57) v1(172.78,78.18) v1(172.78,76.42) v1(172.78,74.67) v1(173.11,79.08) v1(173.11,77.33) v1(173.11,75.57) v1(173.54,78.18) v1(173.54,76.42) v1(173.54,74.67) v1(173.88,79.08) v1(173.88,77.33) v1(173.88,75.57) v1(174.31,78.18) v1(174.31,76.42) v1(174.31,74.67) v1(197.41,73.58) v1(197.5,71.77) v1(197.84,72.67) v1(198.17,73.58) v1(198.26,71.77) v1(198.6,72.67) v1(198.93,73.58) v1(199.03,71.77) v1(199.36,72.67) v1(199.69,73.58) v1(199.79,71.77) v1(200.12,72.67) v1(200.45,73.58) v1(200.55,71.77) v1(201.3,79.08) v1(201.3,77.33) v1(201.3,75.57) v1(201.73,78.18) v1(201.73,76.42) v1(201.73,74.67) v1(202.07,79.08) v1(202.07,77.33) v1(202.07,75.57) v1(202.49,78.18) v1(202.49,76.42) v1(202.49,74.67) v1(202.83,79.08) v1(202.83,77.33) v1(202.83,75.57) v1(203.26,78.18) v1(203.26,76.42) v2(38.61,137.67) v2(38.61,135.13) v2(38.61,132.59) v2(38.61,130.05) v2(38.61,127.51) v2(38.61,124.97) v2(38.61,109.73) v2(38.61,107.19) v2(38.61,104.65) v2(38.61,99.57) v2(38.61,97.03) v2(38.61,94.49) v2(38.61,91.95) v2(38.61,89.41) v2(41.15,137.67) v2(41.15,124.97) v2(41.15,109.73) v2(41.15,107.19) v2(41.15,104.65) v2(41.15,99.57) v2(41.15,97.03) v2(41.15,94.49) v2(41.15,91.95) v2(41.15,89.41) v2(43.69,124.97) v2(43.69,109.73) v2(43.69,107.19) v2(43.69,104.65) v2(43.69,99.57) v2(43.69,97.03) v2(43.69,94.49) v2(43.69,91.95) v2(43.69,89.41) v2(43.69,84.33) v2(43.69,81.79) v2(43.69,71.88) v2(46.23,109.73) v2(46.23,107.19) v2(46.23,104.65) v2(46.23,99.57) v2(46.23,97.03) v2(46.23,94.49) v2(46.23,91.95) v2(46.23,89.41) v2(46.23,84.33) v2(46.23,81.79) v2(46.23,79.25) v2(46.23,76.71) v2(46.23,74.17) v2(46.23,71.88) v2(48.77,137.67) v2(48.77,124.97) v2(48.77,109.73) v2(48.77,107.19) v2(48.77,104.65) v2(48.77,102.11) v2(48.77,99.57) v2(48.77,84.33) v2(48.77,81.79) v2(48.77,79.25) v2(48.77,76.71) v2(48.77,74.17) v2(48.77,71.88) v2(51.31,137.67) v2(51.31,135.13) v2(51.31,127.51) v2(51.31,124.97) v2(53.78,112.56) v2(53.78,111.24) v2(53.78,110.02) v2(53.85,137.67) v2(53.85,135.13) v2(53.85,132.59) v2(53.85,130.05) v2(53.85,127.51) v2(53.85,124.97) v2(54.91,112.56) v2(54.91,110.02) v2(55.01,111.24) v2(56.39,137.67) v2(56.39,135.13) v2(56.39,132.59) v2(56.39,130.05) v2(56.39,127.51) v2(56.39,124.97) v2(58.93,137.67) v2(58.93,135.13) v2(58.93,132.59) v2(58.93,130.05) v2(58.93,127.51) v2(58.93,124.97) v2(61.47,137.67) v2(61.47,135.13) v2(61.47,132.59) v2(61.47,130.05) v2(61.47,127.51) v2(61.47,124.97) v2(64.01,137.67) v2(64.01,135.13) v2(64.01,132.59) v2(64.01,130.05) v2(64.01,127.51) v2(64.01,124.97) v2(66.02,112.37) v2(66.02,110.99) v2(66.02,109.83) v2(66.55,137.67) v2(66.55,135.13) v2(66.55,132.59) v2(66.55,130.05) v2(66.55,127.51) v2(66.55,124.97) v2(66.55,107.19) v2(66.55,104.65) v2(66.55,102.11) v2(66.55,99.57) v2(66.55,97.03) v2(67.24,112.37) v2(67.24,110.99) v2(67.24,109.83) v2(69.09,137.67) v2(69.09,135.13) v2(69.09,132.59) v2(69.09,130.05) v2(69.09,127.51) v2(69.09,124.97) v2(69.09,109.73) v2(69.09,107.19) v2(69.09,104.65) v2(69.09,99.57) v2(69.09,97.03) v2(69.09,94.49) v2(69.09,91.95) v2(69.09,89.41) v2(71.63,137.67) v2(71.63,135.13) v2(71.63,132.59) v2(71.63,130.05) v2(71.63,127.51) v2(71.63,124.97) v2(71.63,109.73) v2(71.63,107.19) v2(71.63,104.65) v2(71.63,99.57) v2(71.63,97.03) v2(71.63,94.49) v2(71.63,91.95) v2(71.63,89.41) v2(74.17,137.67) v2(74.17,135.13) v2(74.17,127.51) v2(74.17,124.97) v2(74.17,109.73) v2(74.17,107.19) v2(74.17,104.65) v2(74.17,99.57) v2(74.17,97.03) v2(74.17,94.49) v2(74.17,91.95) v2(74.17,89.41) v2(75.23,78.06) v2(75.23,75.52) v2(75.23,72.98) v2(76.71,137.67) v2(76.71,124.97) v2(76.71,109.73) v2(76.71,107.19) v2(76.71,104.65) v2(76.71,99.57) v2(76.71,97.03) v2(76.71,94.49) v2(76.71,91.95) v2(76.71,89.41) v2(76.71,79.25) v2(76.71,76.71) v2(76.71,74.17) v2(78.09,112.4) v2(78.12,111.18) v2(78.09,109.86) v2(78.44,77.95) v2(78.44,75.41) v2(78.44,72.87) v2(79.35,112.53) v2(79.35,111.18) v2(79.35,109.99) v2(80.13,79.25) v2(80.13,76.71) v2(80.13,74.17) v2(84.33,137.67) v2(84.33,124.97) v2(86.87,137.67) v2(86.87,135.13) v2(86.87,132.59) v2(86.87,130.05) v2(86.87,127.51) v2(86.87,124.97) v2(89.41,137.67) v2(89.41,135.13) v2(89.41,132.59) v2(89.41,130.05) v2(89.41,127.51) v2(89.41,124.97) v2(90.11,111.36) v2(90.17,112.72) v2(90.17,110.18) v2(91.24,112.72) v2(91.33,111.36) v2(91.24,110.18) v2(91.95,137.67) v2(91.95,135.13) v2(91.95,132.59) v2(91.95,130.05) v2(91.95,127.51) v2(91.95,124.97) v2(94.49,137.67) v2(94.49,135.13) v2(94.49,132.59) v2(94.49,130.05) v2(94.49,127.51) v2(94.49,124.97) v2(97.03,137.67) v2(97.03,135.13) v2(97.03,132.59) v2(97.03,130.05) v2(97.03,127.51) v2(97.03,124.97) v2(99.57,137.67) v2(99.57,135.13) v2(99.57,132.59) v2(99.57,130.05) v2(99.57,127.51) v2(99.57,124.97) v2(102.11,137.67) v2(102.11,135.13) v2(102.11,132.59) v2(102.11,130.05) v2(102.11,127.51) v2(102.11,124.97) v2(102.11,107.19) v2(102.11,104.65) v2(102.11,99.57) v2(102.11,97.03) v2(102.56,112.65) v2(102.59,111.4) v2(102.56,110.11) v2(103.63,112.72) v2(103.63,110.18) v2(103.82,111.4) v2(104.65,137.67) v2(104.65,135.13) v2(104.65,127.51) v2(104.65,124.97) v2(104.65,107.19) v2(104.65,104.65) v2(104.65,99.57) v2(104.65,97.03) v2(104.65,94.49) v2(104.65,91.95) v2(104.65,89.41) v2(104.65,86.87) v2(107.19,137.67) v2(107.19,135.13) v2(107.19,127.51) v2(107.19,124.97) v2(107.19,109.73) v2(107.19,107.19) v2(107.19,104.65) v2(107.19,99.57) v2(107.19,97.03) v2(107.19,94.49) v2(107.19,91.95) v2(107.19,89.41) v2(107.19,86.87) v2(108.32,73.36) v2(108.32,72.08) v2(108.56,81.54) v2(109.73,137.67) v2(109.73,135.13) v2(109.73,132.59) v2(109.73,130.05) v2(109.73,127.51) v2(109.73,124.97) v2(109.73,109.73) v2(109.73,107.19) v2(109.73,104.65) v2(109.73,99.57) v2(109.73,97.03) v2(109.73,94.49) v2(109.73,91.95) v2(109.73,89.41) v2(109.73,86.87) v2(109.67,73.36) v2(109.67,72.08) v2(109.81,81.56) v2(111.1,81.54) v2(111.08,79.18) v2(111.08,77.92) v2(111.08,76.63) v2(111.08,75.39) v2(111.1,74.12) v2(111.08,72.86) v2(112.27,137.67) v2(112.27,135.13) v2(112.27,132.59) v2(112.27,130.05) v2(112.27,127.51) v2(112.27,124.97) v2(112.27,109.73) v2(112.27,107.19) v2(112.27,104.65) v2(112.27,99.57) v2(112.27,97.03) v2(112.27,94.49) v2(112.27,91.95) v2(112.27,89.41) v2(112.27,86.87) v2(112.35,81.56) v2(115.58,112.72) v2(115.55,111.49) v2(115.58,110.18) v2(116.71,112.78) v2(116.77,111.49) v2(128.35,112.9) v2(128.38,111.62) v2(128.35,110.36) v2(129.48,112.97) v2(129.48,110.43) v2(129.61,111.62) v2(130.05,107.19) v2(130.05,104.65) v2(130.05,99.57) v2(132.59,109.73) v2(132.59,107.19) v2(132.59,104.65) v2(132.59,99.57) v2(132.59,94.49) v2(132.59,91.95) v2(132.59,89.41) v2(135.13,109.73) v2(135.13,107.19) v2(135.13,104.65) v2(135.13,99.57) v2(135.13,94.49) v2(135.13,91.95) v2(135.13,89.41) v2(135.13,86.87) v2(137.67,109.73) v2(137.67,107.19) v2(137.67,104.65) v2(137.67,99.57) v2(137.67,94.49) v2(137.67,91.95) v2(137.67,89.41) v2(137.67,86.87) v2(137.67,81.79) v2(137.67,73.22) v2(137.67,71.88) v2(139.23,73.28) v2(139.95,111.4) v2(140.05,112.75) v2(140.05,110.21) v2(140.21,107.19) v2(140.21,104.65) v2(140.21,99.57) v2(140.21,94.49) v2(140.21,91.95) v2(140.21,89.41) v2(140.21,79.25) v2(140.21,76.71) v2(140.21,74.17) v2(141.18,112.72) v2(141.18,111.4) v2(141.18,110.18) v2(142.75,109.73) v2(142.75,107.19) v2(142.75,104.65) v2(142.75,99.57) v2(142.75,81.79) v2(142.75,79.25) v2(142.75,76.71) v2(142.75,74.17) v2(142.79,72.11) v2(144.96,81.77) v2(144.96,79.23) v2(144.96,76.69) v2(144.96,74.15) v2(145.02,72.09) v2(152.2,112.72) v2(152.22,111.33) v2(152.2,110.18) v2(153.2,112.7) v2(153.2,110.16) v2(153.45,111.33) v2(164.03,112.4) v2(164.01,111.11) v2(164.03,109.86) v2(165.07,112.4) v2(165.07,109.86) v2(165.24,111.11) v2(165.61,107.19) v2(165.61,104.65) v2(165.61,99.57) v2(168.15,109.73) v2(168.15,107.19) v2(168.15,104.65) v2(168.15,99.57) v2(168.15,94.49) v2(168.15,91.95) v2(168.15,89.41) v2(170.69,109.73) v2(170.69,107.19) v2(170.69,104.65) v2(170.69,99.57) v2(170.69,94.49) v2(170.69,91.95) v2(170.69,89.41) v2(170.69,86.87) v2(173.23,109.73) v2(173.23,107.19) v2(173.23,104.65) v2(173.23,99.57) v2(173.23,94.49) v2(173.23,91.95) v2(173.23,89.41) v2(173.23,86.87) v2(173.23,84.33) v2(173.23,81.79) v2(173.23,71.88) v2(175.77,107.19) v2(175.77,104.65) v2(175.77,99.57) v2(175.77,94.49) v2(175.77,91.95) v2(175.77,89.41) v2(175.77,86.87) v2(175.77,84.33) v2(175.77,81.79) v2(175.77,79.25) v2(175.77,76.71) v2(175.77,74.17) v2(175.77,71.88) v2(175.87,111.02) v2(175.95,112.31) v2(175.95,109.77) v2(176.92,112.28) v2(176.92,109.74) v2(177.1,111.02) v2(178.31,109.73) v2(178.31,107.19) v2(178.31,104.65) v2(178.31,99.57) v2(178.31,84.33) v2(178.31,81.79) v2(178.31,79.25) v2(178.31,76.71) v2(178.31,74.17) v2(178.31,71.88) v2(187.6,111.05) v2(187.74,112.31) v2(187.74,109.77) v2(188.83,111.05) v2(188.84,112.31) v2(188.84,109.77) v2(196.09,109.73) v2(196.09,107.19) v2(196.09,104.65) v2(196.09,99.57) v2(198.63,109.73) v2(198.63,107.19) v2(198.63,104.65) v2(198.63,99.57) v2(198.63,94.49) v2(198.63,91.95) v2(198.63,89.41) v2(198.63,86.87) v2(201.17,109.73) v2(201.17,107.19) v2(201.17,104.65) v2(201.17,99.57) v2(201.17,94.49) v2(201.17,91.95) v2(201.17,89.41) v2(201.17,86.87) v2(201.81,73.35) v2(201.78,71.96) v2(202.56,81.76) v2(202.56,80.49) v2(203.25,73.39) v2(203.26,71.96) v2(203.71,109.73) v2(203.71,107.19) v2(203.71,104.65) v2(203.71,99.57) v2(203.71,94.49) v2(203.71,91.95) v2(203.71,89.41) v2(204.4,80.49) v2(204.43,79.29) v2(204.42,78.02) v2(204.43,76.75) v2(204.43,74.21) v2(204.43,72.58) v2(204.44,75.48) v2(206.19,80.53) v2(206.25,109.73) v2(206.25,107.19) v2(206.25,104.65) v2(206.25,79.25) v2(206.27,78.02) v2(206.25,76.71) v2(206.24,75.48) v2(206.25,74.17) v2(206.25,72.54) v3(36.67,95.34) v3(36.67,93.31) v3(36.67,89.25) v3(37.18,95.34) v3(37.18,93.31) v3(37.18,89.25) v3(37.94,87.22) v3(38.45,87.22) v3(48.72,96.64) v3(48.72,95.75) v3(48.72,94.86) v3(48.72,93.06) v3(48.72,92.17) v3(48.72,91.28) v3(48.7,89.46) v3(48.7,88.58) v3(48.7,87.69) v3(49.22,96.64) v3(49.22,95.75) v3(49.22,94.86) v3(49.22,93.06) v3(49.22,92.17) v3(49.22,91.28) v3(49.21,89.46) v3(49.21,88.58) v3(49.21,87.69) v3(65.62,95.34) v3(65.62,93.31) v3(65.62,89.25) v3(66.13,95.34) v3(66.13,93.31) v3(66.13,89.25) v3(66.89,87.22) v3(67.4,87.22) v3(80.47,96.48) v3(80.47,95.59) v3(80.47,94.7) v3(80.47,92.85) v3(80.47,91.96) v3(80.45,91.22) v3(80.49,89.21) v3(80.49,88.32) v3(80.49,87.43) v3(80.97,96.48) v3(80.97,95.59) v3(80.97,94.7) v3(80.98,92.85) v3(80.98,91.96) v3(81,89.21) v3(81,88.32) v3(81,87.43) v3(101.19,95.34) v3(101.19,93.31) v3(101.19,89.25) v3(101.69,95.34) v3(101.69,93.31) v3(101.69,89.25) v3(102.46,87.22) v3(102.96,87.22) v3(113.23,96.65) v3(113.23,95.76) v3(113.23,94.87) v3(113.22,93.06) v3(113.22,92.17) v3(113.22,91.29) v3(113.22,89.46) v3(113.22,88.58) v3(113.22,87.69) v3(113.72,93.06) v3(113.72,92.17) v3(113.72,91.29) v3(113.72,89.46) v3(113.72,88.58) v3(113.72,87.69) v3(113.74,96.65) v3(113.74,95.76) v3(113.74,94.87) v3(130.14,95.34) v3(130.14,93.31) v3(130.14,89.25) v3(130.64,95.34) v3(130.64,93.31) v3(130.64,89.25) v3(131.41,87.22) v3(131.91,87.22) v3(145.12,96.6) v3(145.12,95.71) v3(145.12,94.82) v3(145.12,93.02) v3(145.12,92.13) v3(145.07,91.2) v3(145.12,89.4) v3(145.12,88.51) v3(145.12,87.62) v3(145.63,96.6) v3(145.63,95.71) v3(145.63,94.82) v3(145.63,93.02) v3(145.63,92.13) v3(145.63,91.21) v3(145.63,89.4) v3(145.63,88.51) v3(145.63,87.62) v3(165.7,95.34) v3(165.7,93.31) v3(165.7,89.25) v3(166.21,95.34) v3(166.21,93.31) v3(166.21,89.25) v3(166.97,87.22) v3(167.48,87.22) v3(177.7,96.67) v3(177.7,95.78) v3(177.7,94.89) v3(177.73,93.08) v3(177.73,92.19) v3(177.73,91.3) v3(177.73,89.46) v3(177.73,88.58) v3(177.73,87.69) v3(178.21,96.67) v3(178.21,95.78) v3(178.21,94.89) v3(178.24,93.08) v3(178.24,92.19) v3(178.24,91.3) v3(178.24,89.46) v3(178.24,88.58) v3(178.24,87.69) v3(194.65,95.34) v3(194.65,93.31) v3(194.65,89.25) v3(195.16,95.34) v3(195.16,93.31) v3(195.16,89.25) v3(195.92,87.22) v3(196.43,87.22) v3(206.67,96.68) v3(206.67,95.79) v3(206.67,94.9) v3(206.68,93.08) v3(206.68,92.19) v3(206.68,91.3) v3(206.68,89.46) v3(206.68,88.58) v3(206.68,87.69) v3(207.18,96.68) v3(207.18,95.79) v3(207.18,94.9) v3(207.19,93.08) v3(207.19,92.19) v3(207.19,91.3) v3(207.19,89.46) v3(207.19,88.58) v3(207.19,87.69)

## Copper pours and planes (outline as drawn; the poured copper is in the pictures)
PGND on TOP: 1.27,138.43 227.33,138.43 227.33,1.27 1.27,1.27 ; 30 cut-outs
PGND on BOTTOM: 1.27,138.43 1.27,1.27 227.33,1.27 227.33,138.43 ; 43 cut-outs
PGND on L2_PWR: 1.27,138.43 1.27,1.27 227.33,1.27 227.33,138.43 ; 22 cut-outs
PGND on L2_PWR, L3_PWR: 110.82,54.8 124.05,54.8 124.05,48.28 132.3,48.28 132.3,22.19 99.89,22.19 99.89,42.27 105.35,42.27 105.35,49.33
PGND on L3_PWR: 1.27,138.43 1.27,1.27 227.33,1.27 227.33,138.43 ; 23 cut-outs
PGND on L4_PWR: 1.27,138.43 1.27,1.27 227.33,1.27 227.33,138.43 ; 24 cut-outs
PGND on L5_GND: 1.27,138.43 1.27,1.27 227.33,1.27 227.33,138.43 ; 51 cut-outs
PGND on L6_SIG: 1.27,138.43 227.33,138.43 227.33,1.27 1.27,1.27 ; 65 cut-outs
PGND on L7_SIG: 1.27,138.43 227.33,138.43 227.33,1.27 1.27,1.27 ; 69 cut-outs
V5 on TOP: 104.91,28.44 104.91,27.03 105.9,27.03 105.9,28.44
V5 on TOP: 109.88,48.24 109.88,49.03 106.87,49.03 106.87,48.24
V5 on TOP: 109.07,28.44 109.07,27.03 110.06,27.03 110.06,28.44
V5 on TOP: 122.5,38.94 122.06,38.5 122.06,36.71 123.44,36.71 123.44,38.94
V5 on BOTTOM: 225.92,26.24 225.92,27.78 224.41,27.78 224.41,26.24
_N2 on TOP: 123.44,35.01 123.44,33.96 122.06,33.96 122.06,35.01
_N4 on TOP: 127.71,34.28 127.71,33.29 129.69,33.29 129.69,34.28
_N5 on TOP: 107.27,30.14 107.27,29.35 104.91,29.35 104.91,30.14
_N7 on TOP: 123.44,35.34 123.44,36.33 122.06,36.33 122.06,35.34
_N8 on TOP: 127.63,35.65 127.63,34.66 129.69,34.66 129.69,35.65
_N9 on TOP: 125.93,42.89 125.93,47.01 126.97,47.01 126.97,42.89
_N20 on TOP: 125.88,42.51 125.88,38.62 126.92,38.62 126.92,42.51
_N30 on TOP: 106.02,38.16 106.02,37.02 104.68,37.02 104.13,36.47 103.18,36.47 102.97,36.27 102.97,34.24 100.76,34.24 100.76,38.16
_N31 on TOP: 127.71,33.03 127.71,31.95 128.8,30.85 129.76,30.85 129.76,33.03
_N32 on TOP: 131.39,33.03 131.39,29.86 130.4,29.86 130.4,33.03
_N45 on TOP: 127.63,35.9 127.63,38.09 128.37,38.09 128.77,38.49 129.81,38.49 129.81,35.9
_N47 on TOP: 130.42,35.9 130.42,39.48 131.69,39.48 131.69,35.9
_N76 on TOP: 110.06,29.35 110.06,30.14 107.7,30.14 107.7,29.35
_N79 on TOP: 122.53,43.23 122.53,45.47 123.31,45.47 123.31,43.23
_N86 on TOP: 122.5,40.72 122.5,42.13 123.44,42.13 123.44,40.72
_N109 on BOTTOM: 13.08,31.11 13.08,27.7 12.29,27.7 12.29,30.01 12.04,30.26 11.25,30.26 11.25,31.25 13,33.01 15.13,33.01 15.13,32.07 14.03,32.07
_N111 on BOTTOM: 14.78,27.7 13.99,27.7 13.99,29.65 15.54,29.65 16.75,30.86 16.75,33.36 17.08,33.36 17.08,30
_N115 on TOP: 34.13,83.85 34.13,85.57 34.76,85.57 34.76,83.85
_N120 on TOP: 36.8,84.51 36.8,85.15 35.14,85.15 35.14,84.51
_N122 on TOP: 38.78,84.51 38.78,85.15 37.05,85.15 37.05,84.51
_N129 on TOP: 39.24,84.71 42.82,84.71 42.82,81.13 39.24,81.13
_N129 on TOP: 28.61,70.12 50.13,70.12 50.13,62.07 28.61,62.07
_N129 on TOP: 41.23,78.68 41.23,79.84 38.94,79.84 38.94,78.68
_N129 on TOP, BOTTOM: 33.58,73.97 33.58,75.13 29.98,75.13 29.98,73.97
_N129 on TOP, BOTTOM: 33.58,77.83 33.58,78.53 29.98,78.53 29.98,77.83
_N129 on TOP, BOTTOM: 42.57,76.98 42.57,77.68 38.97,77.68 38.97,76.98
_N129 on TOP, BOTTOM: 42.57,75.28 42.57,75.98 38.97,75.98 38.97,75.28
_N129 on TOP, BOTTOM: 33.58,76.13 33.58,76.83 29.98,76.83 29.98,76.13
_N129 on BOTTOM: 41.29,78.68 41.29,79.84 38.92,79.84 38.92,78.68
_N129 on BOTTOM: 50.13,70.17 50.13,62.07 28.61,62.07 28.61,65.47 35.8,65.47 36.68,66.35 36.68,67.28 36.55,67.42 35.86,67.42 35.66,67.21 35.66,66.61 35.32,66.27 28.81,66.27 28.61,66.48 28.61,70.17
_N129 on L2_PWR: 36.65,78.53 29.98,78.53 29.98,77.83 33.96,77.83 34.05,77.79 34.09,77.7 36.65,77.7
_N129 on L2_PWR: 41.33,79.84 41.33,78.68 38.94,78.68 38.94,79.84
_N129 on L2_PWR: 31.39,73.97 34.09,73.97 34.09,78.25 36.28,78.25 36.28,84.09 37.92,84.09 37.92,79.84 39.1,79.84 39.1,78.68 38.59,78.68 38.59,71.01 50.13,71.01 50.13,62.07 28.61,62.07 28.61,71.01 31.39,71.01
_N129 on L2_PWR, L3_PWR, L4_PWR: 42.57,76.98 42.57,77.68 38.71,77.68 38.62,77.71 38.59,77.8 37.56,77.8 37.56,76.85 38.59,76.85 38.62,76.94 38.71,76.98
_N129 on L2_PWR, L3_PWR, L4_PWR: 34.68,76.95 34.09,76.95 34.05,76.86 33.96,76.83 29.98,76.83 29.98,76.13 33.96,76.13 34.05,76.09 34.09,76 34.68,76
_N129 on L2_PWR, L3_PWR, L4_PWR: 42.57,75.28 42.57,75.98 38.71,75.98 38.62,76.01 38.59,76.1 37.56,76.1 37.56,75.15 38.59,75.15 38.62,75.24 38.71,75.28
_N129 on L2_PWR, L3_PWR, L4_PWR: 34.64,73.92 34.64,75.25 34.09,75.25 34.05,75.16 33.96,75.13 29.98,75.13 29.98,73.92
_N129 on L3_PWR: 36.28,80.25 38.59,80.25 38.59,71.01 50.13,71.01 50.13,62.07 28.61,62.07 28.61,71.01 31.39,71.01 31.39,73.97 34.09,73.97 34.09,78.25 36.28,78.25
_N129 on L3_PWR: 41.23,78.68 41.23,80.25 37.56,80.25 37.56,78.56 38.59,78.56 38.62,78.65 38.71,78.68
_N129 on L3_PWR, L4_PWR: 36.28,78.53 29.98,78.53 29.98,77.83 33.96,77.83 34.05,77.79 34.09,77.7 36.28,77.7
_N129 on L4_PWR: 36.28,79.84 38.59,79.84 38.59,71.01 50.13,71.01 50.13,62.07 28.61,62.07 28.61,71.01 31.39,71.01 31.39,73.97 34.09,73.97 34.09,78.25 36.28,78.25
_N129 on L4_PWR: 37.56,79.84 41.23,79.84 41.23,78.68 38.71,78.68 38.62,78.65 38.59,78.56 37.56,78.56
_N137 on BOTTOM: 28.61,61.56 50.13,61.56 50.13,54.92 28.61,54.92
_N137 on L2_PWR, L3_PWR, L4_PWR: 28.61,61.56 28.61,54.92 50.13,54.92 50.13,61.56
_N157 on TOP: 63.08,83.85 63.08,85.57 63.71,85.57 63.71,83.85
_N158 on TOP: 65.75,84.51 65.75,85.15 64.1,85.15 64.1,84.51
_N159 on TOP: 67.73,84.51 67.73,85.15 66,85.15 66,84.51
_N163 on TOP: 68.19,84.71 71.77,84.71 71.77,81.13 68.19,81.13
_N163 on TOP: 57.56,70.12 79.08,70.12 79.08,62.07 57.56,62.07
_N163 on TOP: 70.18,78.68 70.18,79.84 67.89,79.84 67.89,78.68
_N163 on TOP, BOTTOM: 62.53,76.13 62.53,76.83 58.94,76.83 58.94,76.13
_N163 on TOP, BOTTOM: 62.53,77.83 62.53,78.53 58.94,78.53 58.94,77.83
_N163 on TOP, BOTTOM: 71.52,75.28 71.52,75.98 67.92,75.98 67.92,75.28
_N163 on TOP, BOTTOM: 71.52,76.98 71.52,77.68 67.92,77.68 67.92,76.98
_N163 on TOP, BOTTOM: 62.53,73.97 62.53,75.13 58.94,75.13 58.94,73.97
_N163 on BOTTOM: 70.23,78.68 70.23,79.84 67.89,79.84 67.89,78.68
_N163 on BOTTOM: 79.08,70.17 79.08,62.07 57.56,62.07 57.56,65.49 60.03,65.49 60.05,65.46 64.69,65.46 65.75,66.52 65.75,67.38 65.72,67.41 64.69,67.41 64.69,66.73 64.41,66.45 57.56,66.45 57.56,70.17
_N163 on L2_PWR: 70.26,78.68 70.26,80.25 66.51,80.25 66.51,78.56 67.54,78.56 67.58,78.65 67.66,78.68
_N163 on L2_PWR: 66.87,80.25 67.54,80.25 67.54,71.01 79.08,71.01 79.08,62.07 57.56,62.07 57.56,71.01 60.34,71.01 60.34,73.97 63.04,73.97 63.04,78.25 65.23,78.25 65.23,84.09 66.87,84.09
_N163 on L2_PWR, L3_PWR, L4_PWR: 63.59,73.92 63.59,75.25 63.04,75.25 63.01,75.16 62.92,75.13 58.94,75.13 58.94,73.92
_N163 on L2_PWR, L3_PWR, L4_PWR: 71.52,75.28 71.52,75.98 67.66,75.98 67.58,76.01 67.54,76.1 66.51,76.1 66.51,75.15 67.54,75.15 67.58,75.24 67.66,75.28
_N163 on L2_PWR, L3_PWR, L4_PWR: 71.52,76.98 71.52,77.68 67.66,77.68 67.58,77.71 67.54,77.8 66.51,77.8 66.51,76.85 67.54,76.85 67.58,76.94 67.66,76.98
_N163 on L2_PWR, L3_PWR, L4_PWR: 65.23,78.53 58.94,78.53 58.94,77.83 62.92,77.83 63.01,77.79 63.04,77.7 65.23,77.7
_N163 on L2_PWR, L3_PWR, L4_PWR: 63.63,76.95 63.04,76.95 63.01,76.86 62.92,76.83 58.94,76.83 58.94,76.13 62.92,76.13 63.01,76.09 63.04,76 63.63,76
_N163 on L3_PWR: 70.18,78.68 70.18,80.25 66.51,80.25 66.51,78.56 67.54,78.56 67.58,78.65 67.66,78.68
_N163 on L3_PWR: 65.23,80.25 67.54,80.25 67.54,71.01 79.08,71.01 79.08,62.07 57.56,62.07 57.56,71.01 60.34,71.01 60.34,73.97 63.04,73.97 63.04,78.25 65.23,78.25
_N163 on L4_PWR: 65.23,79.84 67.54,79.84 67.54,71.01 79.08,71.01 79.08,62.07 57.56,62.07 57.56,71.01 60.34,71.01 60.34,73.97 63.04,73.97 63.04,78.25 65.23,78.25
_N163 on L4_PWR: 66.51,79.84 70.18,79.84 70.18,78.68 67.66,78.68 67.58,78.65 67.54,78.56 66.51,78.56
_N164 on BOTTOM, L2_PWR, L3_PWR, L4_PWR: 57.56,61.56 57.56,54.92 79.08,54.92 79.08,61.56
_N189 on TOP: 98.64,83.85 98.64,85.57 99.28,85.57 99.28,83.85
_N190 on TOP: 101.31,84.51 101.31,85.15 99.66,85.15 99.66,84.51
_N191 on TOP: 103.29,84.51 103.29,85.15 101.57,85.15 101.57,84.51
